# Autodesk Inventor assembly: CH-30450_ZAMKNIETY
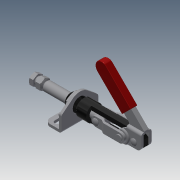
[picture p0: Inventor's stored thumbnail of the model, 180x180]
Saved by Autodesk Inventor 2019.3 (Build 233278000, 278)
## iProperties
Company: ·L?¤¤?
Created: 2010-06
Part Number: CH-30450_ZAMKNIETY
Material: Ogólny
Description: STEP AP203
Document SubType Name: Assembly
Designer: CADENGINEERING4
Sending System: SolidWorks 2005179
Preprocessor: SwSTEP 2.0
Title: CH-30450.STEP
Author: ·L?¥Î?
Revision Number: ANY
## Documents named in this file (13)
- D:\Vault_2016\Projekty\STRONA\Push-pull clamp\CH-30450\CH-30450_ZAMKNIETY.iam
- D:\Vault_2016\Projekty\STRONA\Push-pull clamp\CH-30450\CH-30450-04___.ipt
- D:\Vault_2016\Projekty\STRONA\Push-pull clamp\CH-30450\CH-30450-10___.ipt
- D:\Vault_2016\Projekty\STRONA\Push-pull clamp\CH-30450\CH-30450-08___.ipt
- D:\Vault_2016\Projekty\STRONA\Push-pull clamp\CH-30450\CH-30450-07___.ipt
- D:\Vault_2016\Projekty\STRONA\Push-pull clamp\CH-30450\CH-30450-05___.ipt
- D:\Vault_2016\Projekty\STRONA\Push-pull clamp\CH-30450\CH-30450-09___.ipt
- D:\Vault_2016\Projekty\STRONA\Push-pull clamp\CH-30450\CH-30450-06___.ipt
- D:\Vault_2016\Projekty\STRONA\Push-pull clamp\CH-30450\M12X30___.ipt
- D:\Vault_2016\Projekty\STRONA\Push-pull clamp\CH-30450\CH-30450-02___.ipt
- D:\Vault_2016\Projekty\STRONA\Push-pull clamp\CH-30450\M12___.ipt
- D:\Vault_2016\Projekty\STRONA\Push-pull clamp\CH-30450\CH-30450-01___.ipt
- D:\Vault_2016\Projekty\STRONA\Push-pull clamp\CH-30450\CH-30450-03___.ipt
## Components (14 placed, 14 different names)
1. CH-30450-04_??_1
2. CH-30450-10_??_2
3. CH-30450-08_??_3
4. CH-30450-07_??_4
5. CH-30450-05_??_5
6. CH-30450-09_??_6
7. CH-30450-06_??_7
8. M12X30_??_8
9. CH-30450-02_??_9
10. M12_??_10
11. CH-30450-07_??_11
12. CH-30450-01_??_12
13. CH-30450-03_??_13
14. CH-30450-04_??_14
